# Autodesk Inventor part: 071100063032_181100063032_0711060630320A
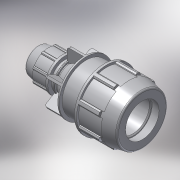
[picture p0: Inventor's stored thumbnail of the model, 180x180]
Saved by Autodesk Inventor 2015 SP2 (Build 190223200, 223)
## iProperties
Created: 2017-02
Part Number: 071100063032_181100063032_0711060630320A
Material: PVC-Piping
Description: PLASSON REDUCING COUPLER 63-32
Document SubType Name: Modeling
Designer: KIM
Mass: 92.6774 g
Surface Area: 199.44 cm^2
Volume: 66.1981 cm^3
Density: 1.4 g/cm^3
Appearance: Smooth - White
Author: KIM
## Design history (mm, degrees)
derived "07110.ipt"
feature "Solid1::07110.ipt"
tag "TaggingFeature1"
body "Solid1"
other parameters: "d2" = 63, "d4" = 16.41667, "d5" = 28.14286, "d7" = 113, "d9" = 28.14286, "d11" = 2.81429, "d12" = 90.4, "d13" = 120 deg, "d14" = 94.5, "d15" = 12 deg, "d16" = 101.7, "d18" = 3.15, "d19" = 35 deg, "d20" = 17.5 deg, "d21" = 105.09, "d23" = 0, "d25" = 360 deg, "d27" = 2.26, "d42" = 43.34, "d46" = 1.89, "d51" = 197, "d52" = 28.14286, "d53" = 12 deg, "d56" = 48, "d57" = 32, "d58" = 56.7, "d59" = 28.8, "d60" = 57.6, "d61" = 51.2, "d62" = 19.7, "d63" = 31.52, "d64" = 120 deg, "d65" = 64, "d68" = 14.07143, "d74" = 59.52, "d75" = 35 deg, "d76" = 17.5 deg, "d78" = 0, "d80" = 360 deg, "d85" = 1.28, "d88" = 0.64, "d93" = 62, "d94" = 79.1, "d97" = 3.2, "d98" = 4.26667, "d99" = 0, "d100" = 4.52, "d102" = 360 deg, "d104" = 2, "d106" = 0, "d107" = 4.26667, "d108" = 0, "d109" = 4.26667, "d110" = 0, "d_" = 63, "E_" = 113, "H_" = 197, "d_1" = 32, "E_1" = 64, "l_1" = 62, "d96" = 9.6
